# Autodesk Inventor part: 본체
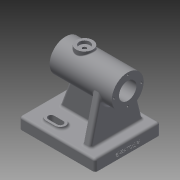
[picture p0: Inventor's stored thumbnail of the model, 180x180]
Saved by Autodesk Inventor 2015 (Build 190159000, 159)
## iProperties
Created: 2022-06
Part Number: 본체
Material: 일반
Document SubType Name: Modeling
Designer: 104658
Density: 1 g/cm^3
Appearance: 기본값
Author: 104658
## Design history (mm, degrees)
sketch "스케치1"
  geometry: L1 (-50, -43)-(50, -43); L2 (50, -43)-(50, 43); L3 (50, 43)-(-50, 43); L4 (-50, 43)-(-50, -43); L5 (-50, -43)-(50, 43); L6 (50, -43)-(-50, 43); 1 further point
  constraints: 12 end point, 2 midpoint, 2 parallel, 1 horizontal, 1 perpendicular
  dimensions: "d0" = 100 distance of L2.end L3.end; "d1" = 86 distance of L1.end L2.end
extrude "돌출1" new body sketch "스케치1" distance "d2" = 15; taper "d3" = 0 deg
sketch "스케치2"
  geometry: L1 (-50, -43)-(50, -43) reference; L2 (50, -43)-(50, 43) reference; L3 (50, 43)-(-50, 43) reference; L4 (-50, 43)-(-50, -43) reference; L5 (25, -35)-(35, -35); L6 (35, -35)-(35, 35); L7 (35, 35)-(25, 35); L8 (25, 35)-(25, -35); L9 (25, -35)-(35, 35); L10 (35, -35)-(25, 35); L11 (-35, -5)-(35, -5); L12 (35, -5)-(35, 5); L13 (35, 5)-(-35, 5); L14 (-35, 5)-(-35, -5); L15 (-35, -5)-(35, 5); L16 (35, -5)-(-35, 5); 3 further points
  constraints: 24 end point, 4 midpoint, 4 parallel, 2 horizontal, 2 perpendicular, 1 point on line
  dimensions: "d4" = 15 distance between parallel lines of L2 L6; "d5" = 10 distance of L6.end L7.end; "d6" = 10 distance of L13.end L11.start; "d7" = 43 distance from line of L1 point (0, 0); "d8" = 15 distance between parallel lines of L4 L14; "d9" = 8 distance between parallel lines of L1 L5; "d10" = 8 distance between parallel lines of L3 L7
extrude "돌출2" join sketch "스케치2" distance "d11" = 57; taper "d12" = 0 deg
feature "면 기울기1" dims angle "d13" = 20 deg
sketch "스케치3"
  geometry: L1 (-50, 0)-(-50, 15) reference; L2 (-50, 15)-(-35, 15) reference; L3 (-35, 15)-(-35, 72) reference; L4 (-35, 72)-(14.254, 72) reference; L5 (14.254, 72)-(35, 15) reference; L6 (35, 15)-(50, 15) reference; L7 (50, 15)-(50, 0) reference; L8 (50, 0)-(-50, 0) reference; L9 (-50, 93)-(32, 93); L10 (32, 93)-(32, 72); L11 (32, 72)-(-50, 72); L12 (-50, 72)-(-50, 93); 1 further point
  constraints: 8 end point, 2 parallel, 1 collinear, 1 horizontal, 1 perpendicular, 1 vertical alignment
  dimensions: "d14" = 21 distance of L11.end L9.start; "d15" = 82 distance of L9.start L9.end
revolve "회전1" sketch "스케치3" stored, may be unused: angle "d16" = 90 deg
sketch "스케치4"
  geometry: L1 (-57, 0)-(-57, 14) reference; L2 (15, -8)-(0, -8) reference; L3 (0, -8)-(0, 0) reference; L4 (0, 0)-(-57, 0) reference; L5 (-57, 0)-(-57, 14) reference; L6 (-57, 56)-(-57, 70) reference; L7 (-57, 70)-(0, 70) reference; L8 (0, 70)-(0, 78) reference; L9 (0, 78)-(15, 78) reference; L10 (15, 78)-(15, -8) reference; L11 (0, 0)-(0, 70) reference; L12 (-57, 14)-(0, 0); L13 (-57, 56)-(0, 70); A1 r 21 centre (-57, 35) between (-57, 14) and (-57, 56) reference; A2 r 21 centre (-57, 35) between (-57, 56) and (-57, 14) reference; 1 further point
  constraints: 4 end point
extrude "돌출3" cut sketch "스케치4" stored distance "d17" = 57; taper "d18" = 0 deg
sketch "스케치5"
  geometry: C1 r 21 at (0, 0) reference; 1 further point
hole "구멍1" sketch "스케치5" at (0, 0) diameter "d19" = 23; stored, may be unused: countersink angle "d23" = 90 deg, drill point angle "d25" = 118 deg; dims "d20" = 6, "d21" = 29, "d22" = 62, "d24" = 8
node "작업 평면1"
sketch "스케치6"
  geometry: L1 (32, -21)-(32, 21) reference; C1 r 11 at (7, 0); 1 further point
  constraints: 1 centre point, 1 horizontal alignment
  dimensions: "d27" = 25 distance from line of C1.centre L1; "d28" = 22 diameter of C1
extrude "돌출4" join sketch "스케치6" stored distance "d29" = 57; taper "d30" = 0 deg
sketch "스케치7"
  geometry: C1 r 11 at (0, 0) reference; 1 further point
hole "구멍2" sketch "스케치7" at (0, 0) diameter "d31" = 4.917; stored, may be unused: countersink angle "d35" = 90 deg, drill point angle "d37" = 0 deg; dims "d32" = 12, "d33" = 14, "d34" = 4, "d36" = 17.1
sketch "스케치8"
  geometry: C1 r 11.5 at (0, 0) reference; 2 further points
  constraints: 1 horizontal alignment
  dimensions: "d38" = 18 distance of C1.centre point (-18, 0)
hole "구멍3" sketch "스케치8" at (-18, 0) diameter "d39" = 2.459; stored, may be unused: countersink angle "d43" = 90 deg, drill point angle "d45" = 118 deg; dims "d40" = 8, "d41" = 14, "d42" = 4, "d44" = 10
sketch "스케치9"
  geometry: C1 r 14.5 at (0, 0) reference; 2 further points
  constraints: 1 horizontal alignment
  dimensions: "d49" = 18 distance of C1.centre point (18, 0)
hole "구멍4" sketch "스케치9" at (18, 0) diameter "d50" = 2.459; stored, may be unused: countersink angle "d54" = 90 deg, drill point angle "d56" = 118 deg; dims "d51" = 8, "d52" = 14, "d53" = 4, "d55" = 10
sketch "스케치10"
  geometry: L1 (-50, 43)-(-50, -43) reference; L2 (50, 43)-(-50, 43) reference; L3 (-24, 27)-(-12, 27); L4 (-24, 20)-(-12, 20); L5 (-12, 34)-(-24, 34); A1 r 7 centre (-24, 27) between (-24, 34) and (-24, 20); A2 r 7 centre (-12, 27) between (-12, 20) and (-12, 34); 2 further points
  constraints: 8 end point, 4 point on circle, 4 tangent, 2 centre point, 1 horizontal, 1 midpoint, 1 parallel
  dimensions: "d60" = 12 distance of L3.end L3.start; "d61" = 26 distance from line of L1 L3.start; "d62" = 16 distance from line of L2 L3.start; "d64" = 14 distance between parallel lines of L4 L5
extrude "돌출5" join sketch "스케치10" distance "d65" = 3; taper "d66" = 0 deg
sketch "스케치11"
  geometry: L1 (-12, 27)-(-24, 27); L2 (-12, 31)-(-24, 31); L3 (-24, 23)-(-12, 23); A1 r 7 centre (-12, 27) between (-12, 20) and (-12, 34) reference; A2 r 7 centre (-24, 27) between (-24, 34) and (-24, 20) reference; A3 r 4 centre (-12, 27) between (-12, 23) and (-12, 31); A4 r 4 centre (-24, 27) between (-24, 31) and (-24, 23); 2 further points
  constraints: 8 end point, 4 point on circle, 4 tangent, 2 centre point, 1 horizontal, 1 midpoint, 1 parallel
  dimensions: "d68" = 8 distance between parallel lines of L2 L3
extrude "돌출6" cut sketch "스케치11" stored distance "d69" = 3; taper "d70" = 0 deg
fillet "모깎기1" dims "d71" = 3
fillet "모깎기2" dims "d72" = 3
fillet "모깎기3" dims "d73" = 3
fillet "모깎기4" dims "d74" = 3
fillet "모깎기5" dims "d75" = 3
fillet "모깎기6" dims "d76" = 1
fillet "모깎기7" dims "d77" = 3
sketch "스케치12"
  geometry: L1 (0, 0)-(0, 80) reference; 3 further points
  constraints: 1 horizontal alignment, 1 midpoint, 1 other
  dimensions: "d78" = 6 distance from line of point (-6, 40) L1
feature "엠보싱1" sketch "스케치12" dims "d0" = 100, "d1" = 86, "d4" = 15, "d5" = 10, "d6" = 10, "d7" = 43, "d8" = 15, "d9" = 8, "d10" = 8, "d79" = 0.5, "d80" = 0
node "솔리드1"
pattern_circular "원형 패턴1" dims angle "d47" = 360 deg
pattern_circular "원형 패턴2" dims angle "d58" = 360 deg
mirror "대칭1"
node "절단 모서리 투영1"
node "절단 모서리 투영2"
other parameters: "d26" = -96
